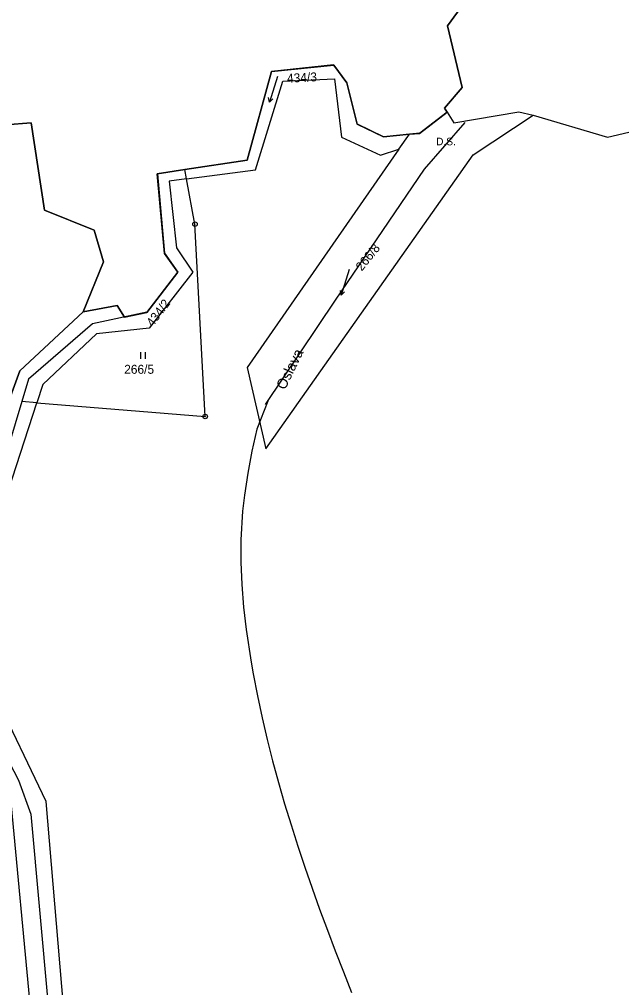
# Model space of a CAD drawing. Extents: x -555757 to -553364, y -1100723 to -1096439.
# Drawn here: x -553793.6 to -553659, y -1098395.8 to -1098179.4 of the extents above; entities that cross this region are included whole.
import ezdxf

# ---------------------------------------------------------------- set-up
doc = ezdxf.new("R2010")
doc.units = 0
for name, color, linetype in [('01_HLADINA', 7, 'Continuous'), ('C$SLO$PARCELY', 7, 'Continuous'), ('HRANICE$PARCELY', 7, 'Continuous'), ('HRANICE_PARCEL', 7, 'Continuous'), ('PLOTY', 7, 'Continuous'), ('SLOUPY', 7, 'Continuous'), ('VSTUP', 7, 'Continuous'), ('ZNA$KY$KULTUR', 7, 'Continuous'), ('zájem', 7, 'Continuous')]:
    doc.layers.add(name, color=color, linetype=linetype)

# ---------------------------------------------------------------- blocks, each defined once
blk = doc.blocks.new('8$02')
at = {"layer": 'ZNA$KY$KULTUR'}
for p, q in [((0.864, 2.855), (-0.89, -2.882)), ((-0.89, -2.882), (-1.083, -1.802)), ((-0.89, -2.882), (-0.125, -2.095))]:
    blk.add_line(p, q, dxfattribs=at)
blk = doc.blocks.new('3$06')
at = {"layer": 'SLOUPY'}
for p, q in [((-0.517, 0.235), (-0.517, 1.735)), ((0.517, 0.235), (0.517, 1.735))]:
    blk.add_line(p, q, dxfattribs=at)
blk = doc.blocks.new('1$05')
at = {"layer": 'SLOUPY'}
for radius in [0.5, 0.032]:
    blk.add_circle((0, 0), radius, dxfattribs=at)

msp = doc.modelspace()

# ---------------------------------------------------------------- linework, layer by layer
at = {"layer": '01_HLADINA'}
for points in [[(-553694.05, -1098202.43), (-553703.11, -1098212.83), (-553723.04, -1098242.14), (-553738.67, -1098265.44)], [(-553738.05, -1098264.73), (-553740.55, -1098270.98), (-553741.61, -1098275.89), (-553742.54, -1098280.81), (-553743.3, -1098285.75), (-553743.7, -1098289.3), (-553744.08, -1098295.7), (-553744.09, -1098300.71), (-553743.88, -1098305.73), (-553743.47, -1098310.74), (-553742.89, -1098315.74), (-553741.78, -1098323.09), (-553741.33, -1098325.67), (-553740.39, -1098330.59), (-553739.36, -1098335.47), (-553738.23, -1098340.31), (-553737.01, -1098345.13), (-553735.71, -1098349.93), (-553734.34, -1098354.7), (-553732.89, -1098359.45), (-553731.38, -1098364.17), (-553729.8, -1098368.89), (-553728.17, -1098373.58), (-553726.49, -1098378.26), (-553724.77, -1098382.94), (-553723, -1098387.6), (-553721.2, -1098392.26), (-553719.37, -1098396.91)]]:
    msp.add_lwpolyline(points, dxfattribs=at)
at = {"layer": 'HRANICE$PARCELY'}
for p, q in [((-553708.77, -1098208.4), (-553706.43, -1098205.05)), ((-553756.23, -1098215.02), (-553756.61, -1098212.96)), ((-553754.34, -1098225.15), (-553756.23, -1098215.02)), ((-553752.06, -1098268.13), (-553754.34, -1098225.15)), ((-553789.65, -1098265.05), (-553793.04, -1098264.77)), ((-553789.65, -1098265.05), (-553752.06, -1098268.13)), ((-553791.27, -1098398.66), (-553795.3, -1098355.18))]:
    msp.add_line(p, q, dxfattribs=at)
for points in [[(-553756.23, -1098215.02), (-553740.84, -1098213), (-553734.75, -1098193.15), (-553723.15, -1098192.68), (-553721.61, -1098205.66), (-553712.91, -1098209.75), (-553708.77, -1098208.4)], [(-553708.77, -1098208.4), (-553742.72, -1098257.2), (-553738.5, -1098275.34), (-553692.17, -1098209.61), (-553678.8, -1098200.76)], [(-553756.23, -1098215.02), (-553760.12, -1098215.53), (-553758.49, -1098230.45), (-553754.82, -1098235.85), (-553764.58, -1098248.38), (-553776.38, -1098249.63), (-553788.33, -1098260.98), (-553789.65, -1098265.05)], [(-553752.26, -1098530.69), (-553770.16, -1098537.71), (-553776.99, -1098536.33), (-553782.27, -1098510.76), (-553785.43, -1098486.14), (-553786.85, -1098463.33), (-553783.9, -1098452.34), (-553783.33, -1098450.22), (-553794.47, -1098414), (-553783.74, -1098399.93), (-553787.56, -1098354.23), (-553799.21, -1098330.05), (-553800.9, -1098317.55), (-553806.65, -1098302.94), (-553796.96, -1098287.57), (-553789.65, -1098265.05)]]:
    msp.add_lwpolyline(points, dxfattribs=at)
at = {"layer": 'HRANICE_PARCEL'}
msp.add_line((-553791, -1098357.06), (-553787.16, -1098399.83), dxfattribs=at)
for points in [[(-553706.43, -1098205.05), (-553712.23, -1098205.59), (-553718.07, -1098202.76), (-553720.38, -1098193.54), (-553723.38, -1098189.52), (-553737.22, -1098191.05), (-553742.67, -1098210.86), (-553756.61, -1098212.96)], [(-553697.98, -1098200.12), (-553704.14, -1098204.83), (-553706.43, -1098205.05)], [(-553697.98, -1098200.12), (-553696.49, -1098202.48), (-553681.97, -1098200.04), (-553678.8, -1098200.76)], [(-553678.8, -1098200.76), (-553662.21, -1098205.7), (-553651.07, -1098203.11), (-553636.4, -1098204.01), (-553617.78, -1098207.06)], [(-553756.61, -1098212.96), (-553762.72, -1098213.88), (-553761.17, -1098231.65), (-553758.19, -1098235.85), (-553765.11, -1098244.84), (-553777.26, -1098247.45), (-553791.55, -1098259.8), (-553793.04, -1098264.77)], [(-553793.04, -1098264.77), (-553798.81, -1098283.98), (-553808.86, -1098298.4), (-553810.17, -1098304.71), (-553805.75, -1098318.12), (-553802.06, -1098333.63), (-553793.8, -1098349.41), (-553791, -1098357.06)]]:
    msp.add_lwpolyline(points, dxfattribs=at)
at = {"layer": 'zájem'}
for points in [[(-553688.18, -1098167.39), (-553697.9, -1098180.8), (-553694.67, -1098194.61), (-553698.63, -1098199.24), (-553697.98, -1098200.12), (-553704.15, -1098204.89), (-553706.44, -1098205.04), (-553712.2, -1098205.59), (-553718.08, -1098202.76), (-553720.4, -1098193.54), (-553723.34, -1098189.57), (-553737.23, -1098191.01), (-553742.7, -1098210.84), (-553756.6, -1098212.95), (-553762.77, -1098213.9), (-553761.18, -1098231.7), (-553758.21, -1098235.89), (-553765.12, -1098244.88), (-553770.09, -1098245.93), (-553771.72, -1098243.29), (-553779.33, -1098244.73), (-553774.8, -1098233.56), (-553776.83, -1098226.45), (-553787.94, -1098222.03), (-553790.97, -1098202.46), (-553796.69, -1098202.96)], [(-553796.19, -1098265.28), (-553793.5, -1098257.9), (-553779.33, -1098244.73), (-553771.72, -1098243.29), (-553770.09, -1098245.93), (-553765.12, -1098244.88), (-553758.21, -1098235.89), (-553761.18, -1098231.7), (-553762.77, -1098213.9), (-553756.6, -1098212.95), (-553742.7, -1098210.84), (-553737.23, -1098191.01), (-553723.34, -1098189.57), (-553720.4, -1098193.54), (-553718.08, -1098202.76), (-553712.2, -1098205.59), (-553706.44, -1098205.04), (-553704.15, -1098204.89), (-553697.98, -1098200.12), (-553698.63, -1098199.24), (-553694.67, -1098194.61), (-553697.9, -1098180.8), (-553688.18, -1098167.39)], [(-553796.85, -1098169.41), (-553801.19, -1098189.94), (-553796.69, -1098202.96), (-553790.97, -1098202.46), (-553787.94, -1098222.03), (-553776.83, -1098226.45), (-553774.8, -1098233.56), (-553779.33, -1098244.73), (-553793.5, -1098257.9), (-553796.19, -1098265.28), (-553801.93, -1098280.68), (-553811.08, -1098291.9), (-553813.65, -1098304.59), (-553832.93, -1098306.52), (-553834.84, -1098309.6), (-553837.04, -1098305.33), (-553848.93, -1098273.99), (-553857.57, -1098247.87), (-553865.26, -1098222.5), (-553872.03, -1098204), (-553873.38, -1098200.91), (-553884.8, -1098171.23)]]:
    msp.add_lwpolyline(points, dxfattribs=at)

# ---------------------------------------------------------------- block references
at = {"layer": 'VSTUP'}
for p in [(-553754.34, -1098225.15), (-553752.06, -1098268.13)]:
    msp.add_blockref('1$05', p, dxfattribs=at)
at = {"layer": 'ZNA$KY$KULTUR'}
for name, p in [('8$02', (-553736.8, -1098195)), ('8$02', (-553720.78, -1098238.17)), ('3$06', (-553765.9, -1098255.52))]:
    msp.add_blockref(name, p, dxfattribs=at)

# ---------------------------------------------------------------- texts
at = {"layer": 'C$SLO$PARCELY'}
for s, rotation, p in [('434/3', 3, (-553733.73, -1098193.54)), ('266/8', 51, (-553717.07, -1098235.76)), ('434/2', 53, (-553763.79, -1098248.22))]:
    msp.add_text(s, height=2, rotation=rotation, dxfattribs=at).set_placement(p)
msp.add_text('266/5', height=2, dxfattribs=at).set_placement((-553770.17, -1098258.59))
at = {"layer": 'PLOTY'}
msp.add_text('D.S.', height=1.7, dxfattribs=at).set_placement((-553700.48, -1098207.51))
msp.add_text('Oslava', height=2.3, rotation=64, dxfattribs=at).set_placement((-553734.24, -1098262.33))

doc.saveas('drawing.dxf')
